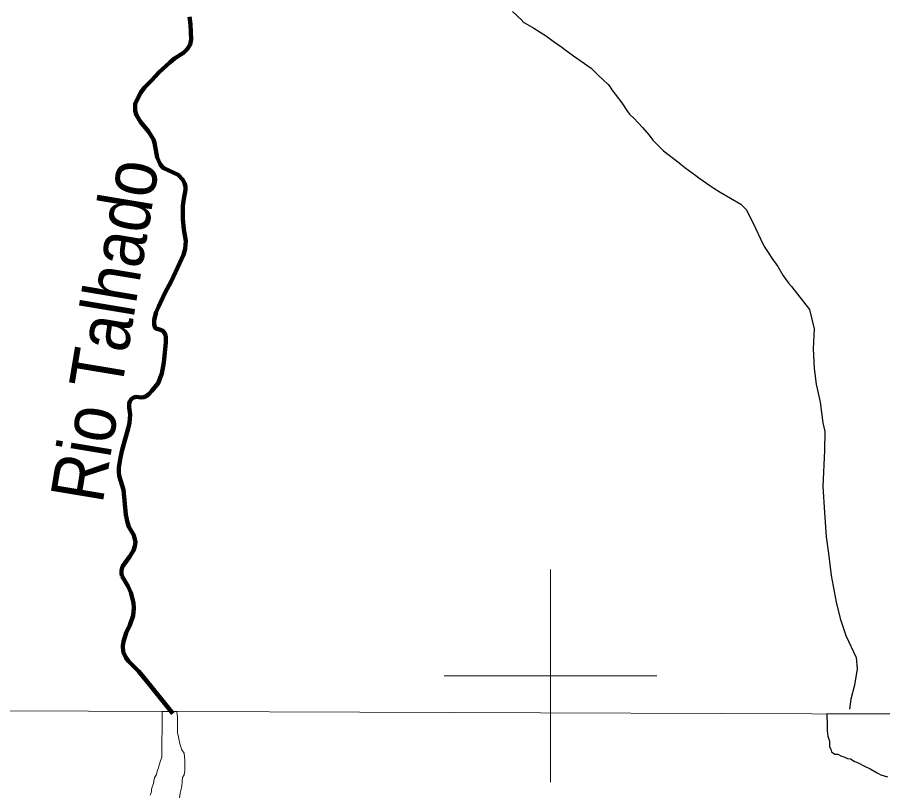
# Model space of a CAD drawing. Extents: x 553962 to 842807, y 8883888 to 9032388.
# Drawn here: x 619982 to 628127, y 8948891 to 8956199 of the extents above; entities that cross this region are included whole.
import ezdxf
from ezdxf.enums import TextEntityAlignment as Align

# ---------------------------------------------------------------- set-up
doc = ezdxf.new("R2010")
doc.units = 0
doc.header["$LTSCALE"] = 20
for name, color, linetype, lineweight in [('1', 7, 'Continuous', 13), ('12', 7, 'Continuous', 25), ('2', 7, 'Continuous', 13), ('21', 7, 'Continuous', 25), ('24', 7, 'Continuous', 25), ('25', 7, 'Continuous', 13), ('9', 7, 'Continuous', 90)]:
    doc.layers.add(name, color=color, linetype=linetype, lineweight=lineweight)
doc.layers.add('49', color=7, linetype='Continuous')

msp = doc.modelspace()

# ---------------------------------------------------------------- linework, layer by layer
at = {"layer": '1'}
msp.add_line((565315.27, 8949866.81), (791497.68, 8949052.23), dxfattribs=at)
at = {"layer": '12'}
for points in [[(624643.77, 8956253.84), (624732.14, 8956169.84), (624741.39, 8956157.84), (624844.77, 8956096.91), (624963.02, 8956020.98), (625024.64, 8955976), (625106.89, 8955919.05), (625134.83, 8955896.05), (625215.83, 8955838.09), (625381.64, 8955722.17), (625453.33, 8955650.17), (625539.39, 8955570.19), (625559.02, 8955549.18), (625578.14, 8955517.16), (625672.33, 8955394.12), (625719.64, 8955321.08), (625744.14, 8955288.07), (625787.21, 8955246.07), (625865.02, 8955162.06), (625928.33, 8955090.05), (625962.83, 8955044.03), (626062.52, 8954941.03)], [(626062.52, 8954941.03), (626210.08, 8954830.09), (626263.58, 8954786.11), (626369.33, 8954710.16), (626395.71, 8954688.16), (626508.64, 8954610.22), (626539.21, 8954592.24), (626598.21, 8954554.27), (626792.14, 8954439.4), (626840.77, 8954390.4), (626864.83, 8954350.38), (626929.46, 8954214.27), (626976.02, 8954113.18), (627012.71, 8954042.13), (627056.27, 8953977.1), (627085.08, 8953931.07), (627140.39, 8953852.04), (627187.39, 8953772.99), (627209.77, 8953739.97), (627243.83, 8953693.95), (627268.08, 8953664.95), (627437.46, 8953449.88)], [(627437.46, 8953449.88), (627481.77, 8953267.66), (627474.21, 8953079.36), (627481.02, 8952894.08), (627502.02, 8952745.88), (627539.46, 8952577.68), (627565.14, 8952382.41), (627583.52, 8952301.32), (627578.89, 8952122.03), (627564.21, 8951783.48), (627577.96, 8951538.12), (627594.52, 8951309.79), (627615.58, 8951152.58), (627641.27, 8950944.29), (627689.96, 8950693.98), (627726.64, 8950540.8), (627780.77, 8950380.63), (627876.21, 8950172.46), (627886.27, 8950067.31), (627860.58, 8949911.03), (627825.71, 8949779.77), (627813.27, 8949686.6)]]:
    msp.add_lwpolyline(points, dxfattribs=at)
at = {"layer": '2'}
for p, q in [((625000, 8949000), (625000, 8951000)), ((624000, 8950000), (626000, 8950000))]:
    msp.add_line(p, q, dxfattribs=at)
at = {"layer": '21'}
msp.add_lwpolyline([(628960.22, 8949636.38), (627600.12, 8949642.89), (627603.71, 8949532.35), (627605.87, 8949482.29), (627610.54, 8949432.22), (627625.21, 8949384.6), (627625.08, 8949364.58), (627627.36, 8949332.03), (627639.71, 8949309.45), (627644.54, 8949284.4), (627676.9, 8949264.21), (627704.39, 8949261.57), (627739.27, 8949243.86), (627761.73, 8949238.74), (627796.63, 8949223.54), (627824.1, 8949218.39), (627858.96, 8949198.19), (627903.83, 8949177.93), (627948.66, 8949152.67), (628014.14, 8949120.81), (628075.72, 8949086.93), (628110.58, 8949066.73), (628172.96, 8949048.88)], dxfattribs=at)
at = {"layer": '24'}
for points in [[(621602.08, 8956204.95), (621612.33, 8956132.85), (621617.21, 8955989.64), (621609.39, 8955942.55), (621581.89, 8955900.44), (621546.46, 8955864.33), (621462.27, 8955810.11), (621421.58, 8955778), (621315.46, 8955681.68), (621248.46, 8955606.45), (621180.33, 8955539.24), (621144.21, 8955490.11), (621090.83, 8955387.86), (621089.58, 8955318.75), (621102.64, 8955276.71), (621141.21, 8955216.68), (621216.21, 8955123.65), (621263.89, 8955050.61), (621273.71, 8955018.58), (621298.39, 8954880.4), (621326.58, 8954818.35), (621344.77, 8954792.34), (621361.21, 8954778.34), (621494.89, 8954716.46), (621540.71, 8954668.45), (621556.46, 8954637.43), (621563.89, 8954607.39), (621564.52, 8954574.34), (621548.77, 8954491.19), (621540.89, 8954424.07), (621539.71, 8954301.88), (621548.02, 8954202.74), (621568.64, 8954096.6), (621562.71, 8954019.47), (621546.96, 8953964.36), (621433.77, 8953717.8), (621371.71, 8953602.52), (621309.64, 8953474.22), (621290.27, 8953424.11), (621271.33, 8953351.97), (621268.46, 8953307.9), (621278.27, 8953276.87), (621286.77, 8953268.87), (621318.52, 8953261.91), (621350.14, 8953247.93), (621369.21, 8953222.93), (621379.58, 8953197.9)], [(621379.58, 8953197.9), (621378.77, 8953137.81), (621359.71, 8952949.48), (621342.39, 8952846.3), (621307.77, 8952755.1), (621249.46, 8952681.89), (621219.14, 8952650.8), (621194.96, 8952631.73), (621171.08, 8952622.68), (621146.21, 8952620.63), (621100.14, 8952625.57), (621079.83, 8952621.53), (621057.02, 8952606.47), (621039.64, 8952581.4), (621035.33, 8952565.37), (621033.58, 8952527.31), (621045.08, 8952461.22), (621037.14, 8952383.09), (621025.71, 8952327.99), (620968.52, 8952127.58), (620952.27, 8952055.44), (620937.46, 8951961.27), (620936.14, 8951922.21), (620941.14, 8951883.16), (620980.27, 8951750.01), (621003.02, 8951516.68), (621017.39, 8951444.59), (621032.46, 8951402.55), (621077.71, 8951325.5), (621094.21, 8951257.42), (621089.39, 8951221.36), (621074.46, 8951180.27), (621037.96, 8951120.12), (620972.83, 8951028.87), (620962.21, 8950992.8), (620961.46, 8950967.76), (620966.27, 8950940.73)], [(620966.27, 8950940.73), (621026.21, 8950839.66), (621050.64, 8950784.62), (621074.21, 8950687.5), (621074.21, 8950687.5), (621078.64, 8950636.43), (621070.96, 8950569.31), (621042.27, 8950477.12), (621007.83, 8950404.96), (620980.77, 8950323.79), (620974.52, 8950282.71), (620979.02, 8950226.63), (621004.64, 8950171.59), (621028.33, 8950139.57), (621075.96, 8950091.57), (621123.99, 8950045.41), (621171.06, 8949985.92), (621444.15, 8949646.58)]]:
    msp.add_lwpolyline(points, dxfattribs=at)
at = {"layer": '25'}
for points in [[(621482.81, 8949664.53), (621346.65, 8949661.52), (621346.41, 8949628.98), (621346.22, 8949603.94), (621346.06, 8949583.92), (621345.82, 8949551.37), (621345.61, 8949523.83), (621345.36, 8949491.29), (621345.11, 8949458.74), (621342.34, 8949423.71), (621342.04, 8949383.66), (621341.83, 8949356.12), (621341.62, 8949328.58), (621341.35, 8949293.54), (621341.1, 8949260.99), (621340.92, 8949235.96), (621330.64, 8949200.98), (621317.85, 8949163.51), (621310.12, 8949133.52), (621297.39, 8949103.56), (621292.14, 8949071.05), (621271.88, 8949038.64), (621266.65, 8949008.63), (621263.98, 8948986.11), (621248.67, 8948946.16), (621240.8, 8948898.64), (621233.13, 8948876.16)], [(621508.07, 8948851.81), (621515.89, 8948894.32), (621521.09, 8948919.32), (621528.93, 8948964.33), (621534.22, 8949001.85), (621537.02, 8949041.89), (621552.22, 8949066.82), (621557.55, 8949109.35), (621557.83, 8949146.9), (621558.12, 8949184.45), (621558.27, 8949204.48), (621556.02, 8949237.04), (621551.28, 8949272.12), (621531.52, 8949304.8), (621519.28, 8949339.92), (621511.93, 8949360), (621509.6, 8949382.55), (621502.27, 8949405.13), (621499.92, 8949425.17), (621492.59, 8949447.75), (621490.26, 8949470.3), (621490.42, 8949490.33), (621490.57, 8949510.35), (621490.72, 8949530.38), (621490.87, 8949550.41), (621491.04, 8949572.94), (621488.79, 8949605.5), (621486.54, 8949638.07), (621484.19, 8949658.11), (621482.81, 8949664.53)]]:
    msp.add_lwpolyline(points, dxfattribs=at)
at = {"layer": '9'}
for points in [[(621602.08, 8956204.95), (621612.33, 8956132.85), (621617.21, 8955989.64), (621609.39, 8955942.55), (621581.89, 8955900.44), (621546.46, 8955864.33), (621462.27, 8955810.11), (621421.58, 8955778), (621315.46, 8955681.68), (621248.46, 8955606.45), (621180.33, 8955539.24), (621144.21, 8955490.11), (621090.83, 8955387.86), (621089.58, 8955318.75), (621102.64, 8955276.71), (621141.21, 8955216.68), (621216.21, 8955123.65), (621263.89, 8955050.61), (621273.71, 8955018.58), (621298.39, 8954880.4), (621326.58, 8954818.35), (621344.77, 8954792.34), (621361.21, 8954778.34), (621494.89, 8954716.46), (621540.71, 8954668.45), (621556.46, 8954637.43), (621563.89, 8954607.39), (621564.52, 8954574.34), (621548.77, 8954491.19), (621540.89, 8954424.07), (621539.71, 8954301.88), (621548.02, 8954202.74), (621568.64, 8954096.6), (621562.71, 8954019.47), (621546.96, 8953964.36), (621433.77, 8953717.8), (621371.71, 8953602.52), (621309.64, 8953474.22), (621290.27, 8953424.11), (621271.33, 8953351.97), (621268.46, 8953307.9), (621278.27, 8953276.87), (621286.77, 8953268.87), (621318.52, 8953261.91), (621350.14, 8953247.93), (621369.21, 8953222.93), (621379.58, 8953197.9)], [(621379.58, 8953197.9), (621378.77, 8953137.81), (621359.71, 8952949.48), (621342.39, 8952846.3), (621307.77, 8952755.1), (621249.46, 8952681.89), (621219.14, 8952650.8), (621194.96, 8952631.73), (621171.08, 8952622.68), (621146.21, 8952620.63), (621100.14, 8952625.57), (621079.83, 8952621.53), (621057.02, 8952606.47), (621039.64, 8952581.4), (621035.33, 8952565.37), (621033.58, 8952527.31), (621045.08, 8952461.22), (621037.14, 8952383.09), (621025.71, 8952327.99), (620968.52, 8952127.58), (620952.27, 8952055.44), (620937.46, 8951961.27), (620936.14, 8951922.21), (620941.14, 8951883.16), (620980.27, 8951750.01), (621003.02, 8951516.68), (621017.39, 8951444.59), (621032.46, 8951402.55), (621077.71, 8951325.5), (621094.21, 8951257.42), (621089.39, 8951221.36), (621074.46, 8951180.27), (621037.96, 8951120.12), (620972.83, 8951028.87), (620962.21, 8950992.8), (620961.46, 8950967.76), (620966.27, 8950940.73)], [(620966.27, 8950940.73), (621026.21, 8950839.66), (621050.64, 8950784.62), (621074.21, 8950687.5), (621074.21, 8950687.5), (621078.64, 8950636.43), (621070.96, 8950569.31), (621042.27, 8950477.12), (621007.83, 8950404.96), (620980.77, 8950323.79), (620974.52, 8950282.71), (620979.02, 8950226.63), (621004.64, 8950171.59), (621028.33, 8950139.57), (621075.96, 8950091.57), (621123.99, 8950045.41), (621171.06, 8949985.92), (621444.15, 8949646.58)]]:
    msp.add_lwpolyline(points, dxfattribs=at)

# ---------------------------------------------------------------- texts
at = {"layer": '49', "width": 0.9}
msp.add_text('Rio Talhado', height=500, rotation=80.538, dxfattribs=at).set_placement((621050.38, 8953212.26), align=Align.CENTER)

doc.saveas('drawing.dxf')
